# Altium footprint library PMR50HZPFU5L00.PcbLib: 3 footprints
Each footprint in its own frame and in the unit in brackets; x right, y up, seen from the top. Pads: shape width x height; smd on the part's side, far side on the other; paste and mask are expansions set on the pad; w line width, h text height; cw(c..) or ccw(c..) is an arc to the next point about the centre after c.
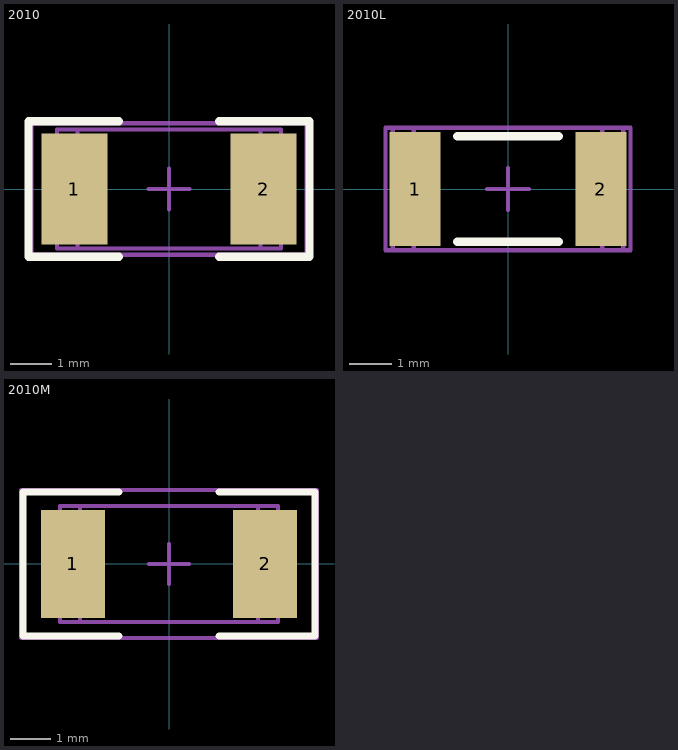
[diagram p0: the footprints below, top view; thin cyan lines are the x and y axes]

## 2010 [mm] "Chip Capacitor, Body 5.08x2.54mm, IPC Medium Density"
height 1.66
pads (2):
  rect 1.6x2.7 smd: 1(-2.3,0) 2(2.3,0)
TopOverlay:
  lines w0.2: -1.219,-1.65 -3.419,-1.65 -3.419,1.65 -1.219,1.65 ; 1.219,-1.65 3.419,-1.65 3.419,1.65 1.219,1.65
Mechanical5:
  lines w0.1: -2.73,-1.45 -2.73,1.45 2.73,1.45 2.73,-1.45 -2.73,-1.45
  text ".Designator" at -1.875,-0.5 h1.02
Mechanical13:
  lines w0.1: -2.23,-1.45 -2.23,1.45 ; 2.23,-1.45 2.23,1.45 ; -2.73,-1.45 2.73,-1.45 2.73,1.45 -2.73,1.45 -2.73,-1.45
Mechanical15:
  lines w0.1: -0.5,0 0.5,0 ; 0,-0.5 0,0.5 ; -3.35,-1.6 3.35,-1.6 3.35,1.6 -3.35,1.6 -3.35,-1.6
3D body: height 1.66, standoff 0, extent -2.729,-1.449 -2.231,1.449
3D body: height 1.66, standoff 0, extent -2.229,-1.449 2.229,1.449
3D body: height 1.66, standoff 0, extent 2.231,-1.449 2.729,1.449

## 2010L [mm]
height 0.71
pads (2):
  rect 1.2x2.7 smd: 1(-2.2,0) 2(2.2,0)
TopOverlay:
  lines w0.2: -1.2,-1.25 1.2,-1.25 ; -1.2,1.25 1.2,1.25
Mechanical5:
  lines w0.1: -2.73,-1.45 -2.73,1.45 2.73,1.45 2.73,-1.45 -2.73,-1.45
  text ".Designator" at -1.875,-0.5 h1.02
Mechanical13:
  lines w0.1: -2.23,-1.45 -2.23,1.45 ; 2.23,-1.45 2.23,1.45 ; -2.73,-1.45 2.73,-1.45 2.73,1.45 -2.73,1.45 -2.73,-1.45
Mechanical15:
  lines w0.1: -0.5,0 0.5,0 ; 0,-0.5 0,0.5 ; -2.9,-1.45 -2.9,1.45 2.9,1.45 2.9,-1.45 -2.9,-1.45
3D body: height 1.66, standoff 0, extent -2.729,-1.449 -2.231,1.449
3D body: height 1.66, standoff 0, extent -2.229,-1.449 2.229,1.449
3D body: height 1.66, standoff 0, extent 2.231,-1.449 2.729,1.449

## 2010M [mm]
height 0.71
pads (2):
  rect 1.6x2.7 smd: 1(-2.4,0) 2(2.4,0)
TopOverlay:
  lines w0.178: -1.25,-1.8 -3.65,-1.8 -3.65,1.8 -1.25,1.8 ; 1.25,-1.8 3.65,-1.8 3.65,1.8 1.25,1.8
Mechanical5:
  lines w0.1: -2.73,-1.45 2.73,-1.45 2.73,1.45 -2.73,1.45 -2.73,-1.45
  text ".Designator" at -1.875,-0.5 h1.02
Mechanical13:
  lines w0.1: -2.23,-1.45 -2.23,1.45 ; 2.23,-1.45 2.23,1.45 ; -2.73,-1.45 2.73,-1.45 2.73,1.45 -2.73,1.45 -2.73,-1.45
Mechanical15:
  lines w0.1: -0.5,0 0.5,0 ; 0,-0.5 0,0.5 ; -3.7,-1.85 3.7,-1.85 3.7,1.85 -3.7,1.85 -3.7,-1.85
3D body: height 1.66, standoff 0, extent -2.729,-1.449 -2.231,1.449
3D body: height 1.66, standoff 0, extent -2.229,-1.449 2.229,1.449
3D body: height 1.66, standoff 0, extent 2.231,-1.449 2.729,1.449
